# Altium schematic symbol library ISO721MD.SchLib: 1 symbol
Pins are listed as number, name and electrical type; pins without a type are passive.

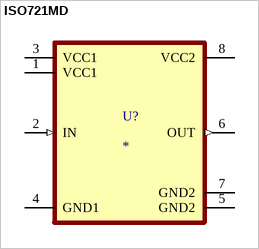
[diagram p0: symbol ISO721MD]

## ISO721MD
designator U?
MP: ISO721MD
footprint ISO721MD
pins: 1 VCC1 (power), 2 IN (in), 3 VCC1 (power), 4 GND1 (power), 5 GND2 (power), 6 OUT (out), 7 GND2 (power), 8 VCC2 (power)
